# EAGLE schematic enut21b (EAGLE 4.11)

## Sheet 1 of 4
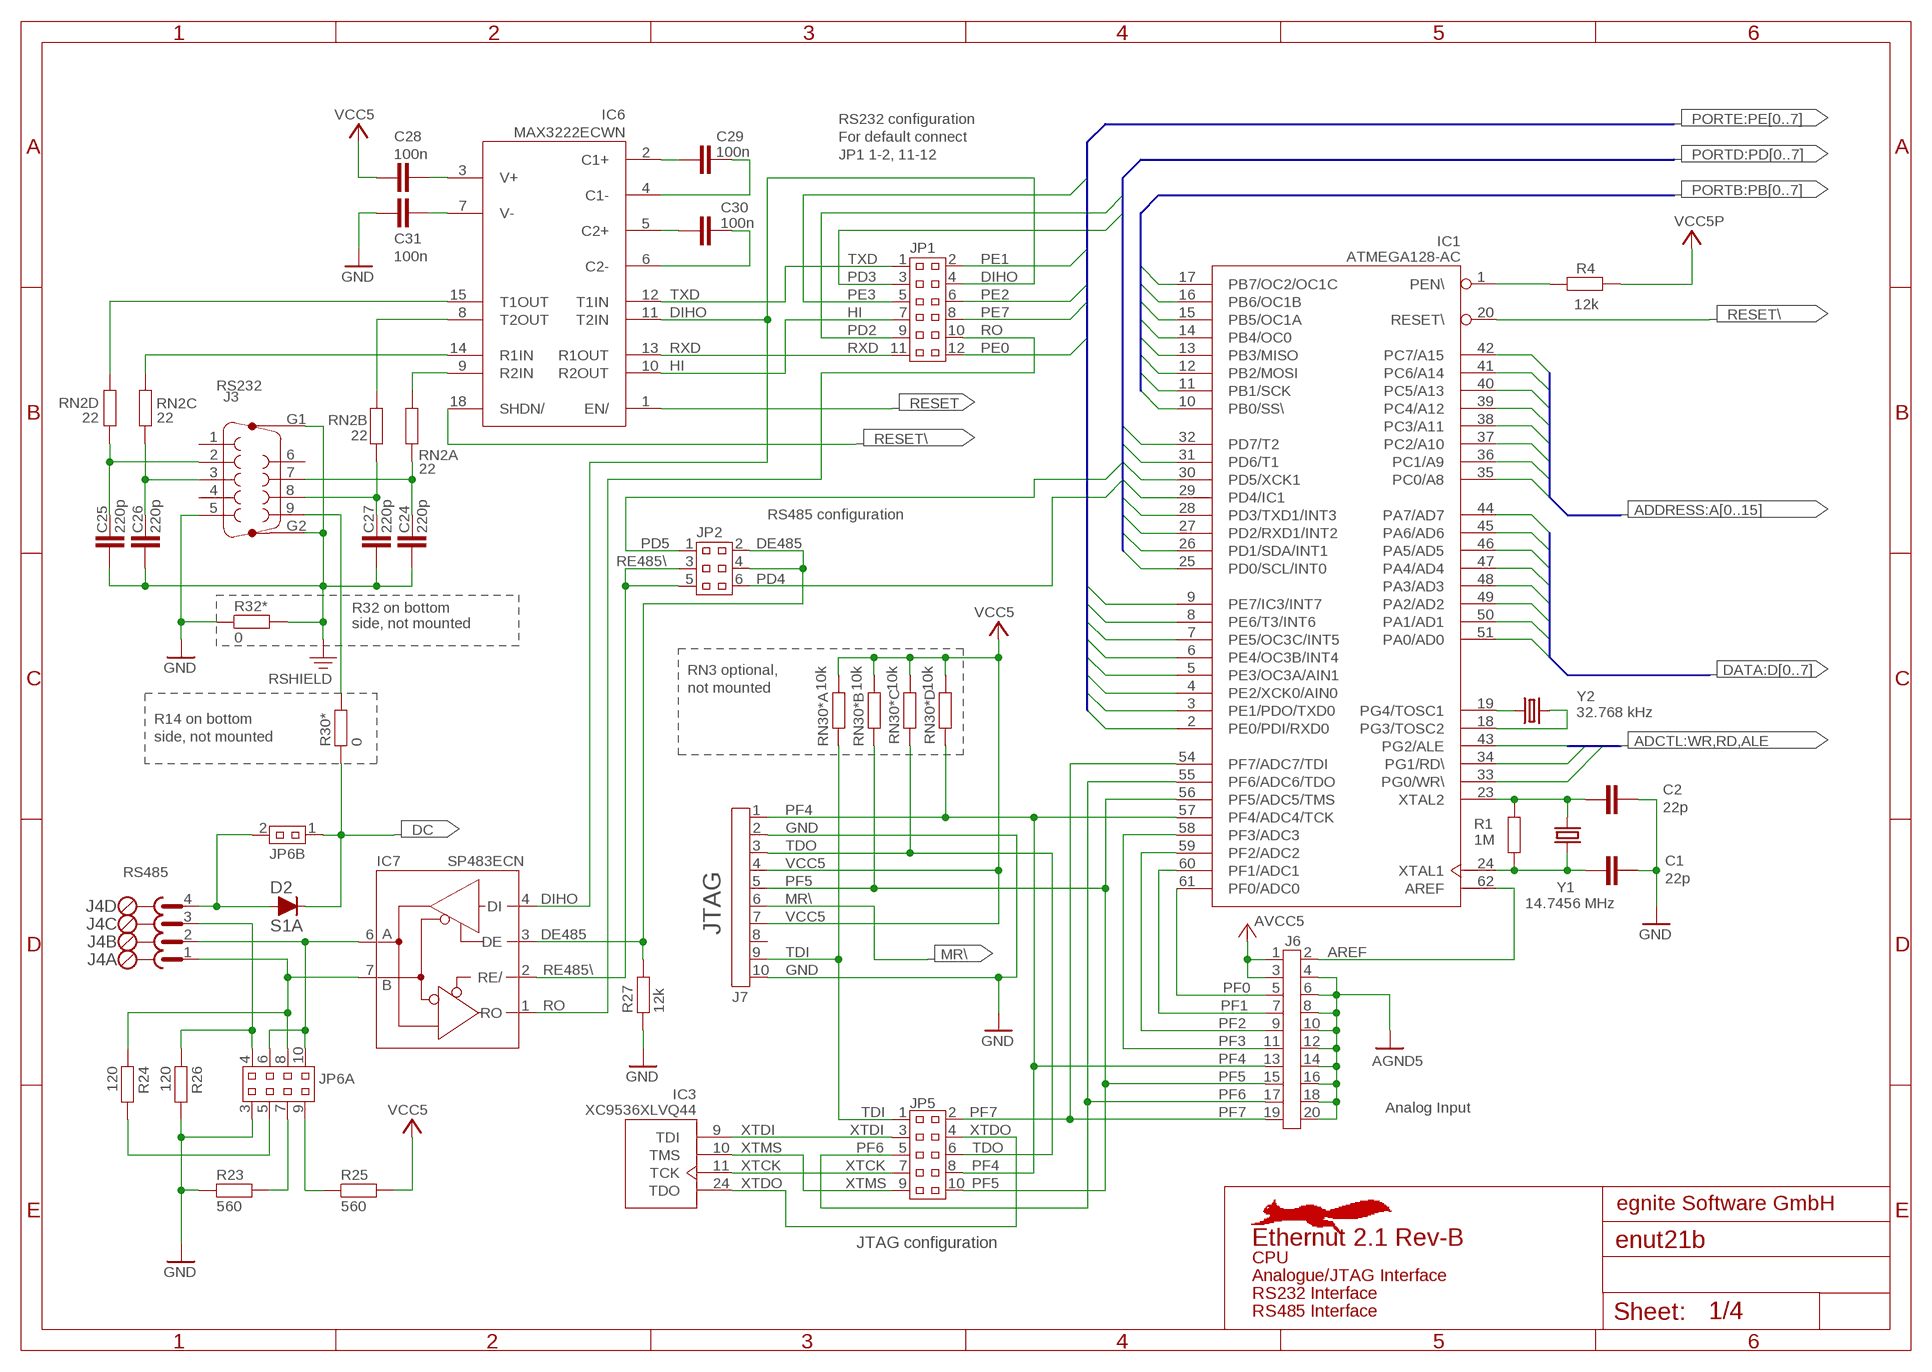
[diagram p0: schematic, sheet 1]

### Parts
C1  22p  C0603  [C0603]
C2  22p  C0603  [C0603]
C24  220p  C0603  [C0603]
C25  220p  C0603  [C0603]
C26  220p  C0603  [C0603]
C27  220p  C0603  [C0603]
C28  100n  C0603  [C0603]
C29  100n  C0603  [C0603]
C30  100n  C0603  [C0603]
C31  100n  C0603  [C0603]
D2  S1A  [SMA]
IC1  ATMEGA128-AC  [TQFP64]
IC3  XC9536XLVQ44  [VQFP44]
IC6  MAX3222ECWN  [SO18W]
IC7  SP483ECN  [SOIC8]
J3  SUBD9F  [SUBD9F]
J4  MINISK  [MINISK]
J6  PIN2X10-2.54  [SLLP2X10]
J7  ML10A  [ML10A]
JP1  JP2X6  [SLY2X6]
JP2  JP2X3  [SLY2X3]
JP5  JP2X5  [SLY2X5]
JP6  JP2X5-1E  [SLY2X5]
R1  1M  R0603  [R0603]
R4  12k  R0603  [R0603]
R23  560  R1206  [R1206]
R24  120  R1206  [R1206]
R25  560  R1206  [R1206]
R26  120  R1206  [R1206]
R27  12k  R0603  [R0603]
R30*  0  R1206  [R1206]
R32*  0  R1206  [R1206]
RN2  22  CAY16  [CAY16]
RN30*  10k  CAY16  [CAY16]
Y1  14.7456 MHz  CRYSTALHC49SM  [HC49SM]
Y2  32.768 kHz  MC-146  [MC-146]

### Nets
A8 [AddrbusH]: IC1.35(PC0/A8) ; also sheet 2
A9 [AddrbusH]: IC1.36(PC1/A9) ; also sheet 2
A10 [AddrbusH]: IC1.37(PC2/A10) ; also sheet 2
A11 [AddrbusH]: IC1.38(PC3/A11) ; also sheet 2
A12 [AddrbusH]: IC1.39(PC4/A12) ; also sheet 2
A13 [AddrbusH]: IC1.40(PC5/A13) ; also sheet 2
A14 [AddrbusH]: IC1.41(PC6/A14) ; also sheet 2
A15 [AddrbusH]: IC1.42(PC7/A15) ; also sheet 2
AGND5: J6.4 J6.6 J6.8 J6.10 J6.12 J6.14 J6.16 J6.18 J6.20 ; also sheet 4
ALE: IC1.43(PG2/ALE) ; also sheet 2
AREF: IC1.62(AREF) J6.2
AVCC5: J6.1 J6.3 ; also sheet 4
D0 [Databus]: IC1.51(PA0/AD0) ; also sheet 2,3
D1 [Databus]: IC1.50(PA1/AD1) ; also sheet 2,3
D2 [Databus]: IC1.49(PA2/AD2) ; also sheet 2,3
D3 [Databus]: IC1.48(PA3/AD3) ; also sheet 2,3
D4 [Databus]: IC1.47(PA4/AD4) ; also sheet 2,3
D5 [Databus]: IC1.46(PA5/AD5) ; also sheet 2,3
D6 [Databus]: IC1.45(PA6/AD6) ; also sheet 2,3
D7 [Databus]: IC1.44(PA7/AD7) ; also sheet 2,3
DC: D2.C JP6.1 R30*.1 ; also sheet 2,4
DCX: D2.A J4.4 JP6.2
DE485: IC7.3(DE) JP2.2 JP2.4 R27.2
DIHO: IC6.11(T2IN) IC7.4(DI) JP1.4
GND: C1.2 C2.2 C31.1 J3.5 J7.2 J7.10 JP6.3 R23.1 R26.2 R27.1 R32*.1 ; also sheet 2,3,4
HI: IC6.10(R2OUT) JP1.7
MR\: J7.6 ; also sheet 2,4
N$1: C28.2 IC6.3(V+)
N$2: J3.9 R30*.2
N$4: IC1.19(PG4/TOSC1) Y2.1
N$6: C2.1 IC1.23(XTAL2) R1.2 Y1.P$2
N$10: C1.1 IC1.24(XTAL1) R1.1 Y1.P$1
N$15: C31.2 IC6.7(V-)
N$20: JP6.9 R25.1
N$23: IC1.18(PG3/TOSC2) Y2.4
N$31: C29.1 IC6.2(C1+)
N$56: C29.2 IC6.4(C1-)
N$57: C30.2 IC6.6(C2-)
N$58: C30.1 IC6.5(C2+)
N$68: JP6.7 R23.2
N$70: JP6.5 R24.2
PB0: IC1.10(PB0/SS\) ; also sheet 2
PB1: IC1.11(PB1/SCK) ; also sheet 2
PB2: IC1.12(PB2/MOSI) ; also sheet 2
PB3: IC1.13(PB3/MISO) ; also sheet 2
PB4: IC1.14(PB4/OC0) ; also sheet 2
PB5: IC1.15(PB5/OC1A) ; also sheet 2
PB6: IC1.16(PB6/OC1B) ; also sheet 2
PB7: IC1.17(PB7/OC2/OC1C) ; also sheet 2
PD0: IC1.25(PD0/SCL/INT0) ; also sheet 2
PD1: IC1.26(PD1/SDA/INT1) ; also sheet 2
PD2: IC1.27(PD2/RXD1/INT2) JP1.9 ; also sheet 2
PD3: IC1.28(PD3/TXD1/INT3) JP1.3 ; also sheet 2
PD4: IC1.29(PD4/IC1) JP2.6 ; also sheet 2
PD5: IC1.30(PD5/XCK1) JP2.1 ; also sheet 2
PD6: IC1.31(PD6/T1) ; also sheet 2
PD7: IC1.32(PD7/T2) ; also sheet 2
PE0: IC1.2(PE0/PDI/RXD0) JP1.12 ; also sheet 2
PE1: IC1.3(PE1/PDO/TXD0) JP1.2 ; also sheet 2
PE2: IC1.4(PE2/XCK0/AIN0) JP1.6 ; also sheet 2
PE3: IC1.5(PE3/OC3A/AIN1) JP1.5 ; also sheet 2
PE4: IC1.6(PE4/OC3B/INT4) ; also sheet 2
PE5: IC1.7(PE5/OC3C/INT5) ; also sheet 2,3
PE6: IC1.8(PE6/T3/INT6) ; also sheet 2,3
PE7: IC1.9(PE7/IC3/INT7) JP1.8 ; also sheet 2
PEN\: IC1.1(PEN\) R4.1
PF0: IC1.61(PF0/ADC0) J6.5
PF1: IC1.60(PF1/ADC1) J6.7
PF2: IC1.59(PF2/ADC2) J6.9
PF3: IC1.58(PF3/ADC3) J6.11
PF4: IC1.57(PF4/ADC4/TCK) J6.13 J7.1 JP5.8 RN30*.4
PF5: IC1.56(PF5/ADC5/TMS) J6.15 J7.5 JP5.10 RN30*.2
PF6: IC1.55(PF6/ADC6/TDO) J6.17 JP5.5
PF7: IC1.54(PF7/ADC7/TDI) J6.19 JP5.2
RD\: IC1.34(PG1/RD\) ; also sheet 2,3
RE485\: IC7.2(RE/) JP2.3 JP2.5
RESET: IC6.1(EN/) ; also sheet 3,4
RESET\: IC1.20(RESET\) IC6.18(SHDN/) ; also sheet 2,4
RO: IC7.1(RO) JP1.10
RS485A: IC7.6(A) J4.2 JP6.6 JP6.10
RS485B: IC7.7(B) J4.1 JP6.8 R24.1
RSHI: IC6.9(R2IN) RN2.8
RSHIELD: C24.2 C25.2 C26.2 C27.2 J3.G1 J3.G2 R32*.2
RSHIF: C24.1 J3.7 RN2.1
RSHO: IC6.8(T2OUT) RN2.7
RSHOF: C27.1 J3.8 RN2.2
RSRXD: IC6.14(R1IN) RN2.6
RSRXDF: C26.1 J3.3 RN2.3
RSTXD: IC6.15(T1OUT) RN2.5
RSTXDF: C25.1 J3.2 RN2.4
RXD: IC6.13(R1OUT) JP1.11
SHLD485: J4.3 JP6.4 R26.1
TDI: J7.9 JP5.1 RN30*.1
TDO: J7.3 JP5.6 RN30*.3
TXD: IC6.12(T1IN) JP1.1
VCC5: C28.1 J7.4 J7.7 R25.2 RN30*.5 RN30*.6 RN30*.7 RN30*.8 ; also sheet 2,4
VCC5P: R4.2 ; also sheet 4
WR\: IC1.33(PG0/WR\) ; also sheet 2,3
XTCK: IC3.11(TCK) JP5.7
XTDI: IC3.9(TDI) JP5.3
XTDO: IC3.24(TDO) JP5.4
XTMS: IC3.10(TMS) JP5.9
Unconnected: J3.1 J3.4 J3.6 J7.8

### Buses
DATA:D[0..7]
ADDRESS:A[0..15]
ADCTL:WR\,RD\,ALE
PORTB:PB[0..7]
PORTD:PD[0..7]
PORTE:PE[0..7]

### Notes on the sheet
- RS232 configuration
- For default connect
- JP1 1-2, 11-12
- RS232
- RS485 configuration
- R32 on bottom
- side, not mounted
- RN3 optional,
- not mounted
- R14 on bottom
- side, not mounted
- RS485
- JTAG
- Analog Input
- egnite Software GmbH
- JTAG configuration | Ethernut 2.1 Rev-B
- CPU
- Analogue/JTAG Interface
- RS232 Interface
- RS485 Interface

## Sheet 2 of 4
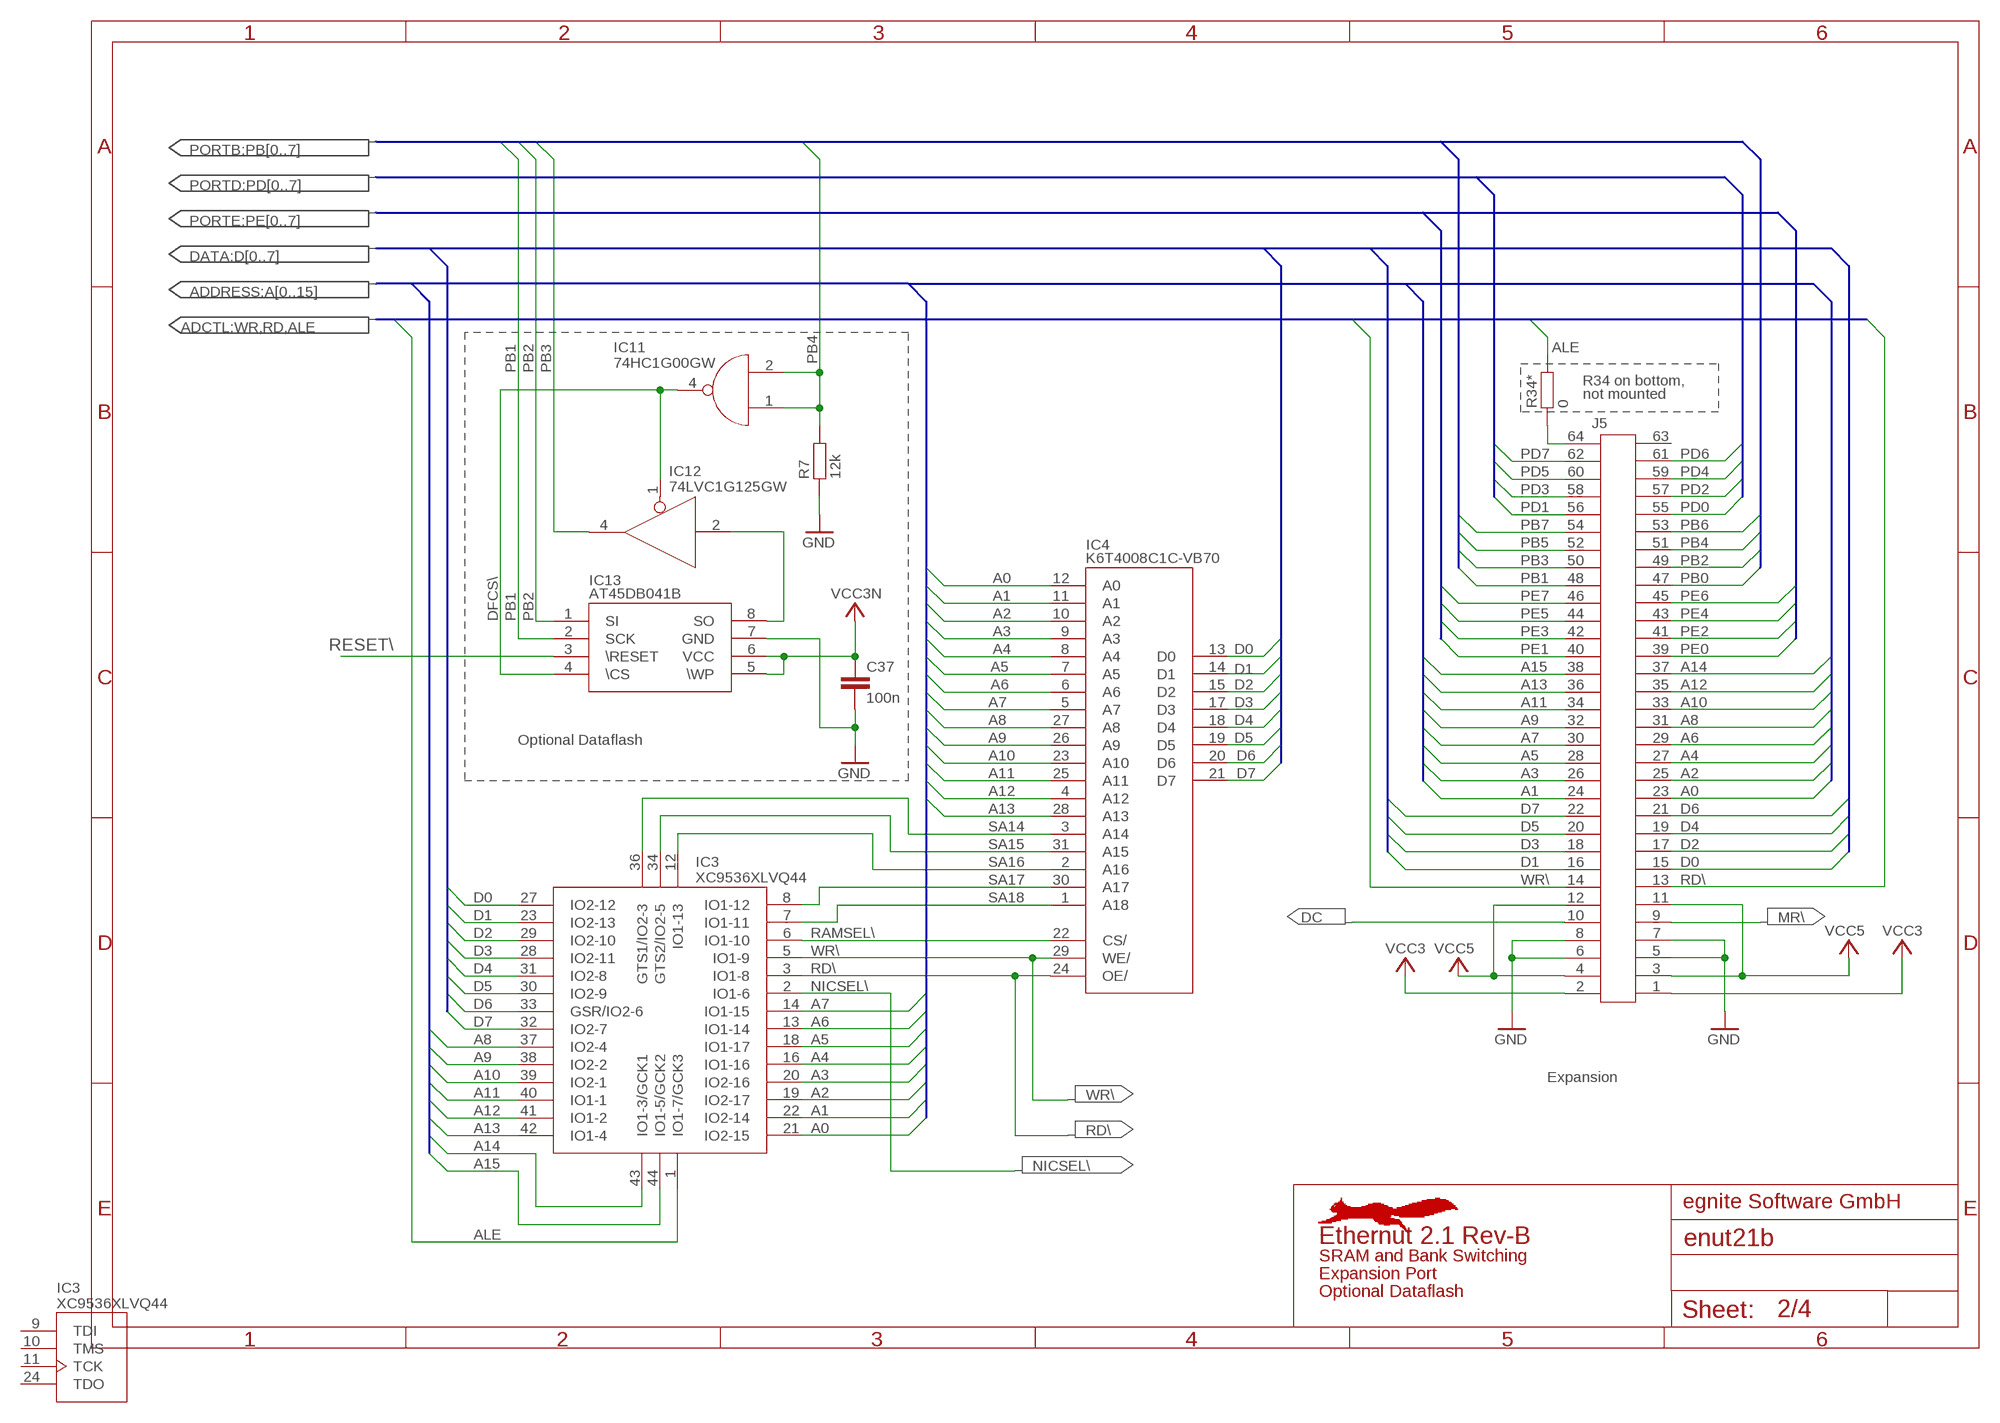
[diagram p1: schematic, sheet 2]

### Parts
C37  100n  C0603  [C0603]
IC4  K6T4008C1C-VB70  [TSOP2-32]
IC11  74HC1G00GW  [SOT353]
IC12  74LVC1G125GW  [SOT353]
IC13  AT45DB041B  [SOIC-8-209]
J5  NUTEXP  [NUTEXP]
R7  12k  R0603  [R0603]
R34*  0  R1206  [R1206]

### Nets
A0: IC3.21(IO2-15) IC4.12(A0) J5.23 ; also sheet 3
A1: IC3.22(IO2-14) IC4.11(A1) J5.24 ; also sheet 3
A2: IC3.19(IO2-17) IC4.10(A2) J5.25 ; also sheet 3
A3: IC3.20(IO2-16) IC4.9(A3) J5.26 ; also sheet 3
A4: IC3.16(IO1-16) IC4.8(A4) J5.27 ; also sheet 3
A5: IC3.18(IO1-17) IC4.7(A5) J5.28
A6: IC3.13(IO1-14) IC4.6(A6) J5.29
A7: IC3.14(IO1-15) IC4.5(A7) J5.30
A8 [AddrbusH]: IC3.37(IO2-4) IC4.27(A8) J5.31 ; also sheet 1
A9 [AddrbusH]: IC3.38(IO2-2) IC4.26(A9) J5.32 ; also sheet 1
A10 [AddrbusH]: IC3.39(IO2-1) IC4.23(A10) J5.33 ; also sheet 1
A11 [AddrbusH]: IC3.40(IO1-1) IC4.25(A11) J5.34 ; also sheet 1
A12 [AddrbusH]: IC3.41(IO1-2) IC4.4(A12) J5.35 ; also sheet 1
A13 [AddrbusH]: IC3.42(IO1-4) IC4.28(A13) J5.36 ; also sheet 1
A14 [AddrbusH]: IC3.43(IO1-3/GCK1) J5.37 ; also sheet 1
A15 [AddrbusH]: IC3.44(IO1-5/GCK2) J5.38 ; also sheet 1
ALE: IC3.1(IO1-7/GCK3) R34*.2 ; also sheet 1
D0 [Databus]: IC3.27(IO2-12) IC4.13(D0) J5.15 ; also sheet 1,3
D1 [Databus]: IC3.23(IO2-13) IC4.14(D1) J5.16 ; also sheet 1,3
D2 [Databus]: IC3.29(IO2-10) IC4.15(D2) J5.17 ; also sheet 1,3
D3 [Databus]: IC3.28(IO2-11) IC4.17(D3) J5.18 ; also sheet 1,3
D4 [Databus]: IC3.31(IO2-8) IC4.18(D4) J5.19 ; also sheet 1,3
D5 [Databus]: IC3.30(IO2-9) IC4.19(D5) J5.20 ; also sheet 1,3
D6 [Databus]: IC3.33(GSR/IO2-6) IC4.20(D6) J5.21 ; also sheet 1,3
D7 [Databus]: IC3.32(IO2-7) IC4.21(D7) J5.22 ; also sheet 1,3
DC: J5.10 ; also sheet 1,4
DFCS\: IC11.4(O) IC12.1(OE) IC13.4(\CS)
DFSO: IC12.2(I) IC13.8(SO)
EXPALE: J5.64 R34*.1
GND: C37.2 IC13.7(GND) J5.5 J5.6 J5.7 J5.8 R7.1 ; also sheet 1,3,4
MR\: J5.9 ; also sheet 1,4
NICSEL\: IC3.2(IO1-6) ; also sheet 3
PB0: J5.47 ; also sheet 1
PB1: IC13.2(SCK) J5.48 ; also sheet 1
PB2: IC13.1(SI) J5.49 ; also sheet 1
PB3: IC12.4(O) J5.50 ; also sheet 1
PB4: IC11.1(I0) IC11.2(I1) J5.51 R7.2 ; also sheet 1
PB5: J5.52 ; also sheet 1
PB6: J5.53 ; also sheet 1
PB7: J5.54 ; also sheet 1
PD0: J5.55 ; also sheet 1
PD1: J5.56 ; also sheet 1
PD2: J5.57 ; also sheet 1
PD3: J5.58 ; also sheet 1
PD4: J5.59 ; also sheet 1
PD5: J5.60 ; also sheet 1
PD6: J5.61 ; also sheet 1
PD7: J5.62 ; also sheet 1
PE0: J5.39 ; also sheet 1
PE1: J5.40 ; also sheet 1
PE2: J5.41 ; also sheet 1
PE3: J5.42 ; also sheet 1
PE4: J5.43 ; also sheet 1
PE5: J5.44 ; also sheet 1,3
PE6: J5.45 ; also sheet 1,3
PE7: J5.46 ; also sheet 1
RAMSEL\: IC3.6(IO1-10) IC4.22(CS/)
RD\: IC3.3(IO1-8) IC4.24(OE/) J5.13 ; also sheet 1,3
RESET\: IC13.3(\RESET) ; also sheet 1,4
SA14: IC3.36(GTS1/IO2-3) IC4.3(A14)
SA15: IC3.34(GTS2/IO2-5) IC4.31(A15)
SA16: IC3.12(IO1-13) IC4.2(A16)
SA17: IC3.8(IO1-12) IC4.30(A17)
SA18: IC3.7(IO1-11) IC4.1(A18)
VCC3: J5.1 J5.2 ; also sheet 4
VCC3N: C37.1 IC13.5(\WP) IC13.6(VCC) ; also sheet 3,4
VCC5: J5.3 J5.4 J5.11 J5.12 ; also sheet 1,4
WR\: IC3.5(IO1-9) IC4.29(WE/) J5.14 ; also sheet 1,3
Unconnected: J5.63

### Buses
ADDRESS:A[0..15]
DATA:D[0..7]
ADCTL:WR\,RD\,ALE
PORTE:PE[0..7]
PORTD:PD[0..7]
PORTB:PB[0..7]

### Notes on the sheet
- R34 on bottom,
- not mounted
- Optional Dataflash
- Expansion
- egnite Software GmbH
- Ethernut 2.1 Rev-B
- SRAM and Bank Switching
- Expansion Port
- Optional Dataflash

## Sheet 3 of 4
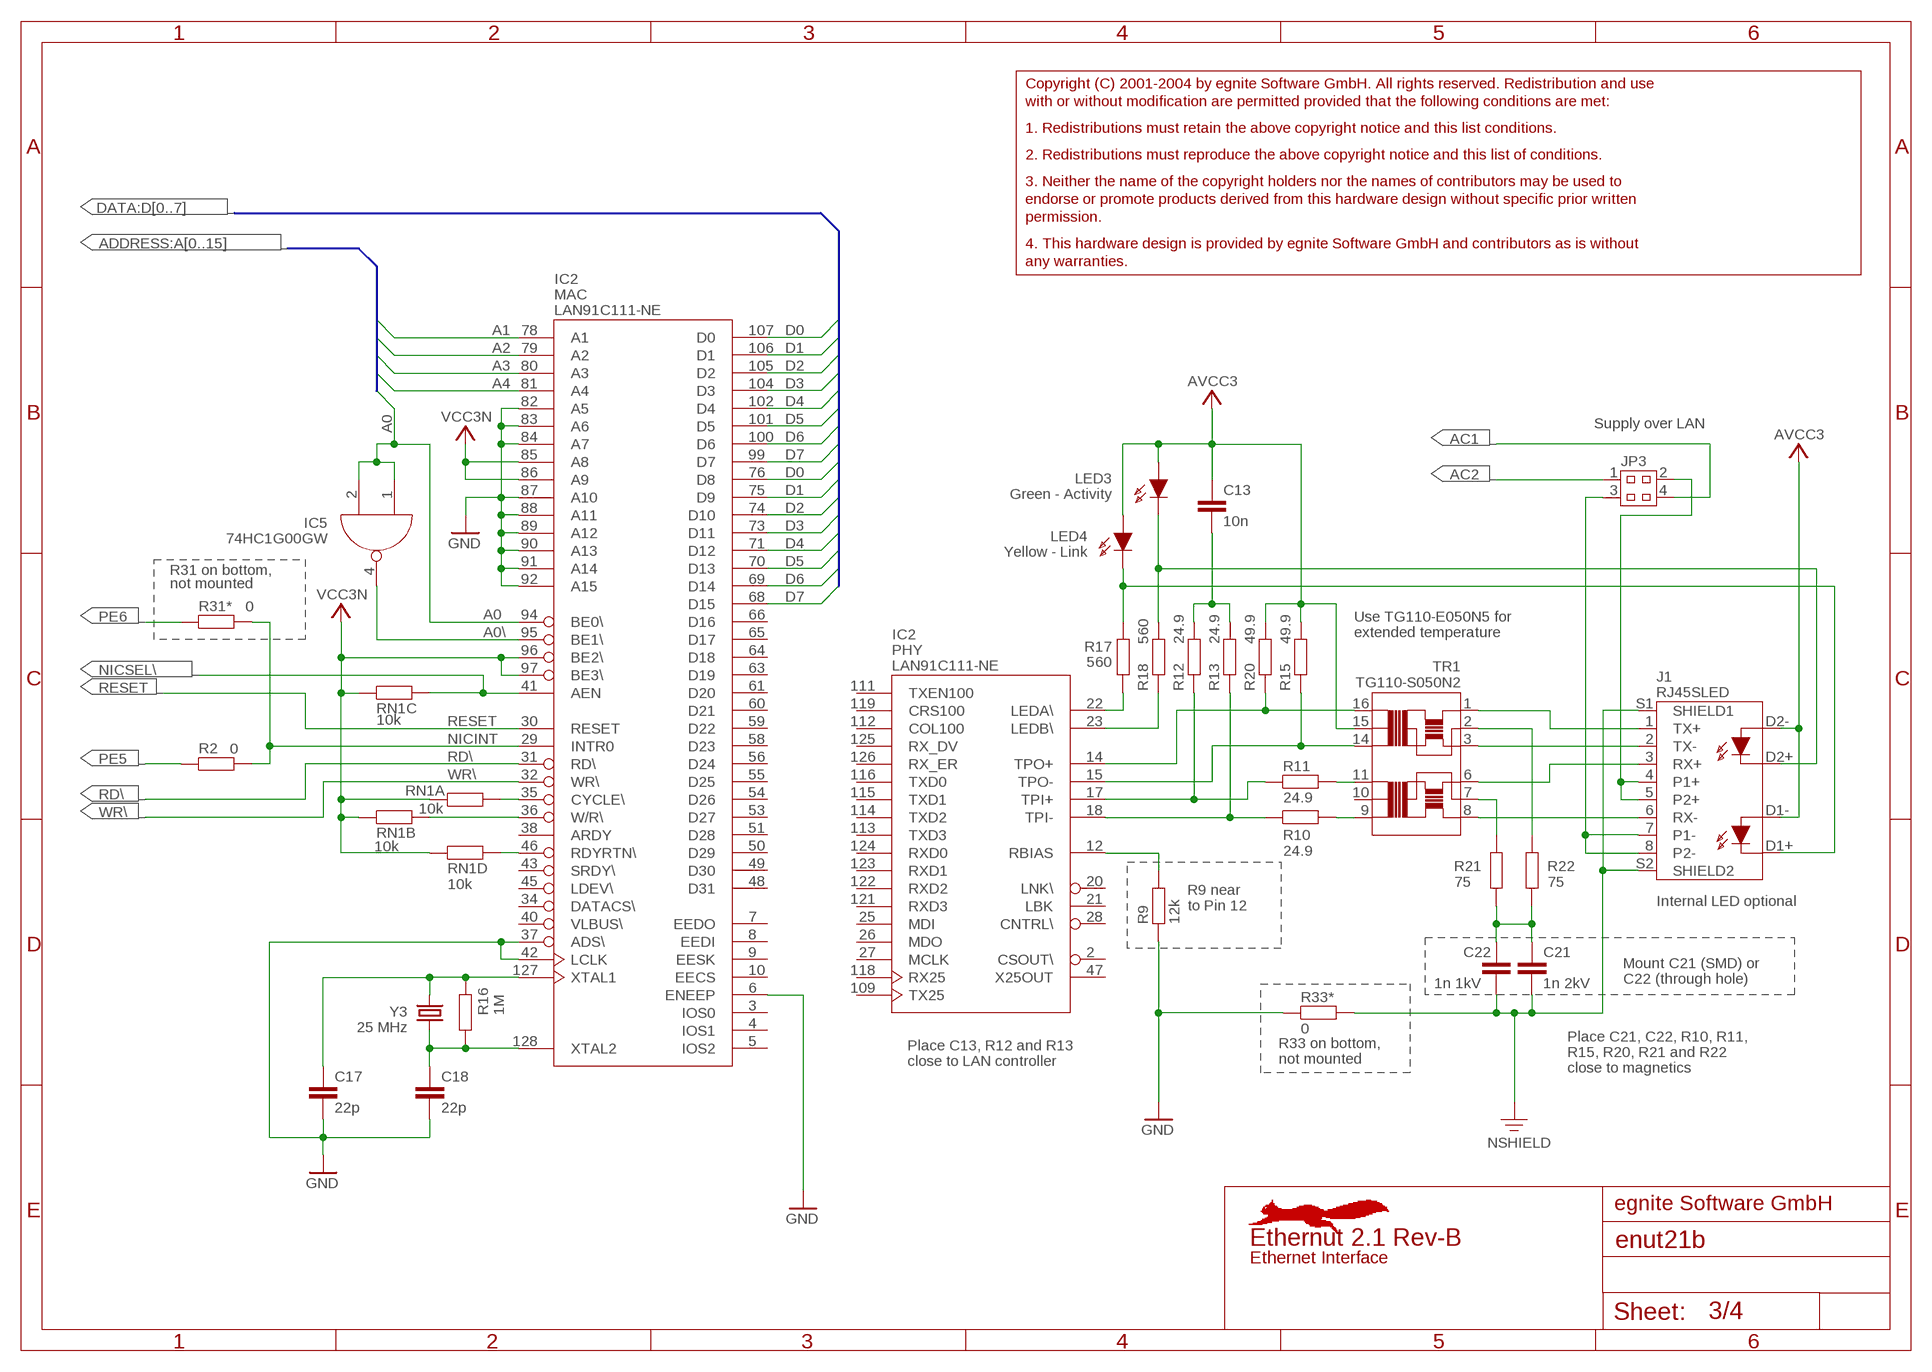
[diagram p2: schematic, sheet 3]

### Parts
C13  10n  C0603  [C0603]
C17  22p  C0603  [C0603]
C18  22p  C0603  [C0603]
C21  1n 2kV  C5.0  [C5.0]
C22  1n 1kV  RCL_C-EUC1812  [RCL_C1812]
IC2  LAN91C111-NE  [TQFP128]
IC5  74HC1G00GW  [SOT353]
J1  RJ45SLED  [RJ45S]
JP3  JP2X2  [SLY2X2]
LED3  LTST-T670KGKT  [P-LCC-2]
LED4  LTST-T670KSKT  [P-LCC-2]
R2  0  R1206  [R1206]
R9  12k  R0603  [R0603]
R10  24.9  R0603  [R0603]
R11  24.9  R0603  [R0603]
R12  24.9  R0603  [R0603]
R13  24.9  R0603  [R0603]
R15  49.9  R0603  [R0603]
R16  1M  R0603  [R0603]
R17  560  R1206  [R1206]
R18  560  R1206  [R1206]
R20  49.9  R0603  [R0603]
R21  75  R1206  [R1206]
R22  75  R1206  [R1206]
R31*  0  R1206  [R1206]
R33*  0  R1206  [R1206]
RN1  10k  CAY16  [CAY16]
TR1  TG110-S050N2  [SOIC16-12TR]
Y3  25 MHz  CRYSTALHC49SM  [HC49SM]

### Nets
A0: IC2.94(MAC:BE0\) IC5.1(I0) IC5.2(I1) ; also sheet 2
A0\: IC2.95(MAC:BE1\) IC5.4(O)
A1: IC2.78(MAC:A1) ; also sheet 2
A2: IC2.79(MAC:A2) ; also sheet 2
A3: IC2.80(MAC:A3) ; also sheet 2
A4: IC2.81(MAC:A4) ; also sheet 2
AC1 [Supply1A]: JP3.4 ; also sheet 4
AC2 [Supply1A]: JP3.1 ; also sheet 4
AVCC3: C13.1 J1.D1-(A1) J1.D2-(A2) LED3.A LED4.A R15.2 R20.2 TR1.15 ; also sheet 4
CYCLE\: IC2.35(MAC:CYCLE\) RN1.8
D0 [Databus]: IC2.76(MAC:D8) IC2.107(MAC:D0) ; also sheet 1,2
D1 [Databus]: IC2.75(MAC:D9) IC2.106(MAC:D1) ; also sheet 1,2
D2 [Databus]: IC2.74(MAC:D10) IC2.105(MAC:D2) ; also sheet 1,2
D3 [Databus]: IC2.73(MAC:D11) IC2.104(MAC:D3) ; also sheet 1,2
D4 [Databus]: IC2.71(MAC:D12) IC2.102(MAC:D4) ; also sheet 1,2
D5 [Databus]: IC2.70(MAC:D13) IC2.101(MAC:D5) ; also sheet 1,2
D6 [Databus]: IC2.69(MAC:D14) IC2.100(MAC:D6) ; also sheet 1,2
D7 [Databus]: IC2.68(MAC:D15) IC2.99(MAC:D7) ; also sheet 1,2
GND: C17.2 C18.2 IC2.6(MAC:ENEEP) IC2.37(MAC:ADS\) IC2.42(MAC:LCLK) IC2.82(MAC:A5) IC2.83(MAC:A6) IC2.84(MAC:A7) IC2.87(MAC:A10) IC2.88(MAC:A11) IC2.89(MAC:A12) IC2.90(MAC:A13) IC2.91(MAC:A14) IC2.92(MAC:A15) R9.1 R33*.1 ; also sheet 1,2,4
LEDA\: J1.D1+(C1) LED4.C R17.2
LEDB\: J1.D2+(C2) LED3.C R18.2
N$5: J1.1(TX+) TR1.1
N$12: J1.2(TX-) TR1.3
N$22: J1.3(RX+) TR1.6
N$24: J1.6(RX-) TR1.8
N$25: IC2.12(PHY:RBIAS) R9.2
N$26: R21.2 TR1.7
N$27: R10.2 TR1.9
N$32: R22.2 TR1.2
N$33: R11.2 TR1.11
N$44: C21.1 C22.1 R21.1 R22.1
NICINT: IC2.29(MAC:INTR0) R2.2 R31*.2
NICSEL\: IC2.41(MAC:AEN) RN1.6 ; also sheet 2
NICWR\: IC2.36(MAC:W/R\) RN1.7
NLEDA\: IC2.22(PHY:LEDA\) R17.1
NLEDB\: IC2.23(PHY:LEDB\) R18.1
NSHIELD: C21.2 C22.2 J1.S1(SHIELD1) J1.S2(SHIELD2) R33*.2
NXTAL1: C17.1 IC2.127(MAC:XTAL1) R16.2 Y3.P$2
NXTAL2: C18.1 IC2.128(MAC:XTAL2) R16.1 Y3.P$1
PE5: R2.1 ; also sheet 1,2
PE6: R31*.1 ; also sheet 1,2
POE+ [Supply1A]: J1.7(P1-) J1.8(P2-) JP3.3
POE- [Supply1A]: J1.4(P1+) J1.5(P2+) JP3.2
RD\: IC2.31(MAC:RD\) ; also sheet 1,2
RDYRTN\: IC2.46(MAC:RDYRTN\) RN1.5
RESET: IC2.30(MAC:RESET) ; also sheet 1,4
RRCUP: C13.2 R12.2 R13.2
TPI+: IC2.17(PHY:TPI+) R11.1 R12.1
TPI-: IC2.18(PHY:TPI-) R10.1 R13.1
TPO+: IC2.14(PHY:TPO+) R20.1 TR1.16
TPO-: IC2.15(PHY:TPO-) R15.1 TR1.14
VCC3N: IC2.85(MAC:A8) IC2.86(MAC:A9) IC2.96(MAC:BE2\) IC2.97(MAC:BE3\) RN1.1 RN1.2 RN1.3 RN1.4 ; also sheet 2,4
WR\: IC2.32(MAC:WR\) ; also sheet 1,2
Unconnected: TR1.10

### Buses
DATA:D[0..7]
ADDRESS:A[0..15]

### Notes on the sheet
- Copyright (C) 2001-2004 by egnite Software GmbH. All rights reserved. Redistribution and use
- with or without modification are permitted provided that the following conditions are met:
- 1. Redistributions must retain the above copyright notice and this list conditions.
- 2. Redistributions must reproduce the above copyright notice and this list of conditions.
- 3. Neither the name of the copyright holders nor the names of contributors may be used to
- endorse or promote products derived from this hardware design without specific prior written
- permission.
- 4. This hardware design is provided by egnite Software GmbH and contributors as is without
- any warranties.
- Supply over LAN
- Green - Activity
- Yellow - Link
- R31 on bottom,
- not mounted
- Use TG110-E050N5 for
- extended temperature
- R9 near
- Internal LED optional
- to Pin 12
- Mount C21 (SMD) or
- C22 (through hole)
- Place C21, C22, R10, R11,
- Place C13, R12 and R13 | R33 on bottom,
- R15, R20, R21 and R22
- close to LAN controller | not mounted
- close to magnetics
- egnite Software GmbH
- Ethernut 2.1 Rev-B
- Ethernet Interface

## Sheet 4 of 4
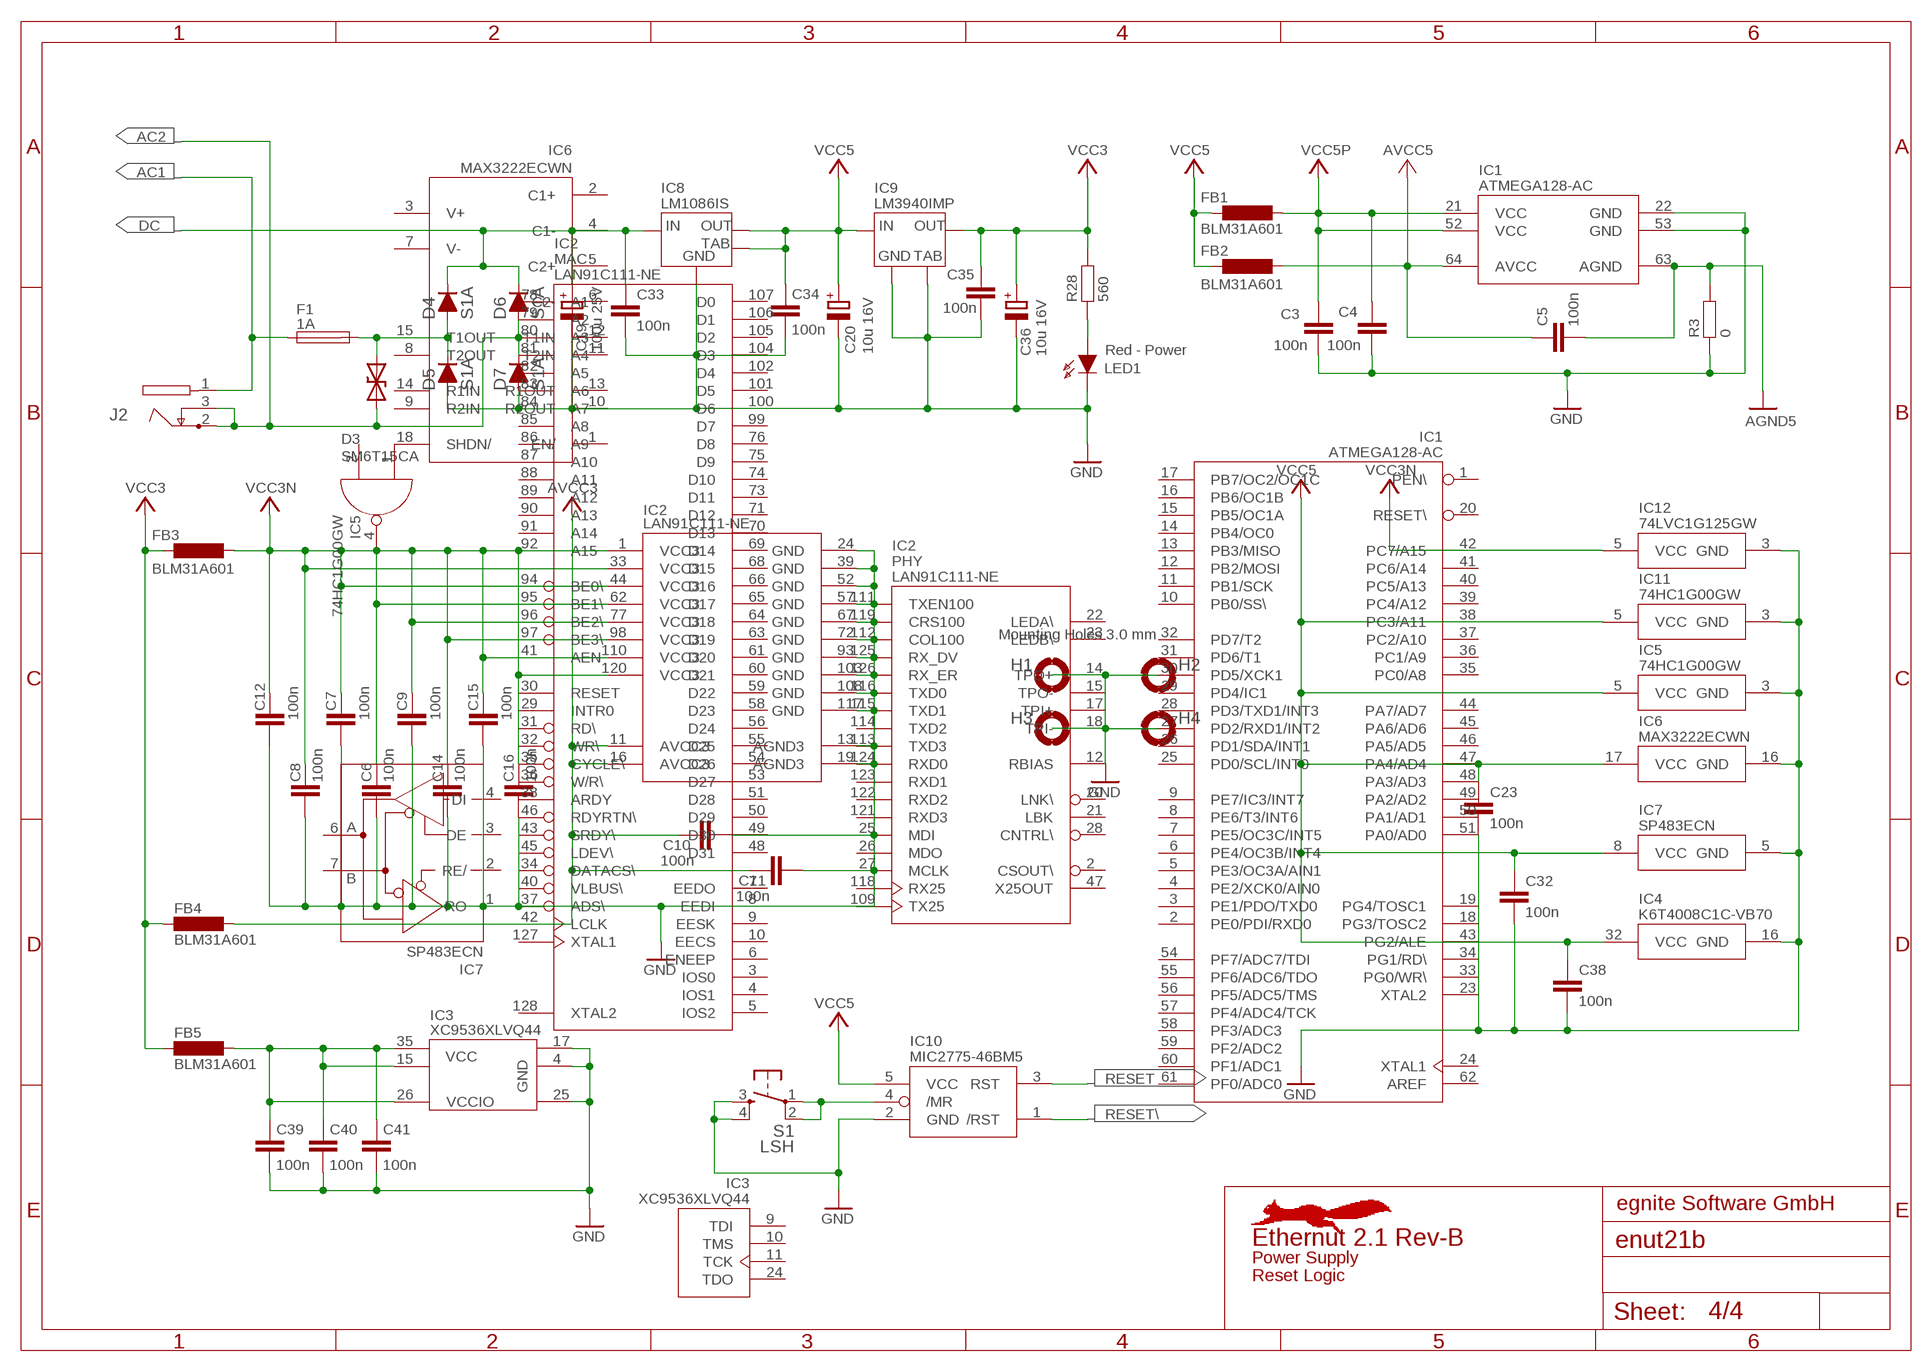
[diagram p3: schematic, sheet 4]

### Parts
C3  100n  C0603  [C0603]
C4  100n  C0603  [C0603]
C5  100n  C0603  [C0603]
C6  100n  C0603  [C0603]
C7  100n  C0603  [C0603]
C8  100n  C0603  [C0603]
C9  100n  C0603  [C0603]
C10  100n  C0603  [C0603]
C11  100n  C0603  [C0603]
C12  100n  C0603  [C0603]
C14  100n  C0603  [C0603]
C15  100n  C0603  [C0603]
C16  100n  C0603  [C0603]
C19  100u 25V  ALUCAP6.3  [ALUC6.3]
C20  10u 16V  ALUCAP4.0  [ALUC4.0]
C23  100n  C0603  [C0603]
C32  100n  C0603  [C0603]
C33  100n  C0603  [C0603]
C34  100n  C0603  [C0603]
C35  100n  C0603  [C0603]
C36  10u 16V  ALUCAP4.0  [ALUC4.0]
C38  100n  C0603  [C0603]
C39  100n  C0603  [C0603]
C40  100n  C0603  [C0603]
C41  100n  C0603  [C0603]
D3  SM6T15CA  SM6T  [SMB]
D4  S1A  [SMA]
D5  S1A  [SMA]
D6  S1A  [SMA]
D7  S1A  [SMA]
F1  1A  OMNI-BLOK  [OMNI-BLOK]
FB1  BLM31A601  BLM31A  [BLM31]
FB2  BLM31A601  BLM31A  [BLM31]
FB3  BLM31A601  BLM31A  [BLM31]
FB4  BLM31A601  BLM31A  [BLM31]
FB5  BLM31A601  BLM31A  [BLM31]
H1  MOUNT3  [MOUNT3]
H2  MOUNT3  [MOUNT3]
H3  MOUNT3  [MOUNT3]
H4  MOUNT3  [MOUNT3]
IC8  LM1086IS  [DDPAK-ST]
IC9  LM3940IMP  [SOT-223]
IC10  MIC2775-46BM5  [SOT23-5L]
J2  DC2.1  [DC2.1]
LED1  LTST-T670KRKT  [P-LCC-2]
R3  0  R1206  [R1206]
R28  560  R1206  [R1206]
S1  LSH  [LSH]

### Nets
AC1 [Supply1A]: F1.1 J2.1 ; also sheet 3
AC2 [Supply1A]: D3.A D6.A D7.C J2.2 J2.3 ; also sheet 3
ACF: D3.C D4.A D5.C F1.2
AGND5: C5.2 IC1.63(AGND) R3.2 ; also sheet 1
AVCC3: C10.1 C11.1 FB4.1 IC2.11(PWR:AVCC3) IC2.16(PWR:AVCC3) ; also sheet 3
AVCC5: C5.1 FB2.2 IC1.64(AVCC) ; also sheet 1
DC: C19.+ C33.1 D4.C D6.C IC8.3(IN) ; also sheet 1,2
GND: C3.2 C4.2 C6.2 C7.2 C8.2 C9.2 C10.2 C11.2 C12.2 C14.2 C15.2 C16.2 C19.- C20.- C23.2 C32.2 C33.2 C34.2 C35.2 C36.- C38.2 C39.2 C40.2 C41.2 D5.A D7.A H1.B3,0(MOUNT) H2.B3,0(MOUNT) H3.B3,0(MOUNT) H4.B3,0(MOUNT) IC1.22(GND) IC1.53(GND) IC2.13(PWR:AGND3) IC2.19(PWR:AGND3) IC2.24(PWR:GND) IC2.39(PWR:GND) IC2.52(PWR:GND) IC2.57(PWR:GND) IC2.67(PWR:GND) IC2.72(PWR:GND) IC2.93(PWR:GND) IC2.103(PWR:GND) IC2.108(PWR:GND) IC2.117(PWR:GND) IC3.4(GND) IC3.17(GND) IC3.25(GND) IC4.16(GND) IC5.3(GND) IC6.16(GND) IC7.5(GND) IC8.1(GND) IC9.2(GND) IC9.4(TAB) IC10.2(GND) IC11.3(GND) IC12.3(GND) LED1.C R3.1 S1.3(S) S1.4(S1) ; also sheet 1,2,3
MR\: IC10.4(/MR) S1.1(P) S1.2(P1) ; also sheet 1,2
N$43: LED1.A R28.1
RESET: IC10.3(RST) ; also sheet 1,3
RESET\: IC10.1(/RST) ; also sheet 1,2
VCC3: C35.1 C36.+ FB3.1 FB4.2 FB5.2 IC9.3(OUT) R28.2 ; also sheet 2
VCC3N: C6.1 C7.1 C8.1 C9.1 C12.1 C14.1 C15.1 C16.1 FB3.2 IC2.1(PWR:VCC3) IC2.33(PWR:VCC3) IC2.44(PWR:VCC3) IC2.62(PWR:VCC3) IC2.77(PWR:VCC3) IC2.98(PWR:VCC3) IC2.110(PWR:VCC3) IC2.120(PWR:VCC3) IC12.5(VCC) ; also sheet 2,3
VCC3X: C39.1 C40.1 C41.1 FB5.1 IC3.15(VCCINT) IC3.26(VCCIO) IC3.35(VCCINT)
VCC5: C20.+ C23.1 C32.1 C34.1 C38.1 FB1.1 FB2.1 IC4.32(VCC) IC5.5(VCC) IC6.17(VCC) IC7.8(VCC) IC8.2(OUT) IC8.4(TAB) IC9.1(IN) IC10.5(VCC) IC11.5(VCC) ; also sheet 1,2
VCC5P: C3.1 C4.1 FB1.2 IC1.21(VCC) IC1.52(VCC) ; also sheet 1
Unconnected: IC2.2(PHY:CSOUT\) IC2.3(MAC:IOS0) IC2.4(MAC:IOS1) IC2.5(MAC:IOS2) IC2.7(MAC:EEDO) IC2.8(MAC:EEDI) IC2.9(MAC:EESK) IC2.10(MAC:EECS) IC2.20(PHY:LNK\) IC2.21(PHY:LBK) IC2.25(PHY:MDI) IC2.26(PHY:MDO) IC2.27(PHY:MCLK) IC2.28(PHY:CNTRL\) IC2.34(MAC:DATACS\) IC2.38(MAC:ARDY) IC2.40(MAC:VLBUS\) IC2.43(MAC:SRDY\) IC2.45(MAC:LDEV\) IC2.47(PHY:X25OUT) IC2.48(MAC:D31) IC2.49(MAC:D30) IC2.50(MAC:D29) IC2.51(MAC:D28) IC2.53(MAC:D27) IC2.54(MAC:D26) IC2.55(MAC:D25) IC2.56(MAC:D24) IC2.58(MAC:D23) IC2.59(MAC:D22) IC2.60(MAC:D21) IC2.61(MAC:D20) IC2.63(MAC:D19) IC2.64(MAC:D18) IC2.65(MAC:D17) IC2.66(MAC:D16) IC2.109(PHY:TX25) IC2.111(PHY:TXEN100) IC2.112(PHY:COL100) IC2.113(PHY:TXD3) IC2.114(PHY:TXD2) IC2.115(PHY:TXD1) IC2.116(PHY:TXD0) IC2.118(PHY:RX25) IC2.119(PHY:CRS100) IC2.121(PHY:RXD3) IC2.122(PHY:RXD2) IC2.123(PHY:RXD1) IC2.124(PHY:RXD0) IC2.125(PHY:RX_DV) IC2.126(PHY:RX_ER)

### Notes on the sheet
- Red - Power
- Mounting Holes 3.0 mm
- egnite Software GmbH
- Ethernut 2.1 Rev-B
- Power Supply
- Reset Logic

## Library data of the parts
C1-C18 C21 C23-C35 C37-C41 = enut202:C: Capacitor
C19 C20 C36 = enut202:ALUCAP: Capacitor Electrolyt
C22 = enut202:RCL_C-EU: CAPACITOR, European symbol
D2 D4-D7 = enut202:S1A: Diode Rectifier
D3 = enut202:SM6T: Bidirectional Transient Voltage Suppressor
F1 = enut202:OMNI-BLOK: Littlefuse OMNI-BLOK Fuseholder with Fuse
FB1-FB5 = enut202:BLM31A: Inductivity Murata
H1-H4 = enut202:MOUNT3: No part, mounting hole
IC1 = enut202:ATMEGA128: IC - Atmel AVR Microcontroller
IC2 = enut202:LAN91C111: SMSC 10/100 Non-PCI Ethernet MAC + PHY
IC3 = enut202:XC9536XL: IC - CPLD, Xlinx 36 macrocells 34 user I/O pins
IC4 = enut202:K6T4008C1C: Samsung SRAM 512k x 8
IC5 IC11 = enut202:74*1G00: IC - Picogate, Philips (Fairchild)
IC6 = enut202:MAX3222E: Maxim RS232 Driver
IC7 = enut202:SP483E: Sipex RS485 Driver
IC8 = enut202:LM1086: National Voltage Regulator
IC9 = enut202:LM3940: National Voltage Regulator
IC10 = enut202:MIC2775-*: Micrel Voltage Supervisor
IC12 = enut202:74*1G125: IC - Picogate, Philips (Fairchild) Bus buffer/line drivers; 3-state
IC13 = enut202:AT45DB041B: IC - Atmel Dataflash
J1 = enut202:RJ45SLED: Connector - RJ45 (NO LED)
J2 = enut202:DC: Connector - DC 2.1 mm
J3 = enut202:SUBD9F: Connector DB-9
J4 = enut202:MINISK: Connector - Phoenix Micro Screw Terminal
J5 = enut202:NUTEXP: Connector - Pin Header
J6 = enut202:PIN2X10: Connector - Pinhead
J7 = enut202:ML10: Connector 10-pin
JP1 = enut202:JP2X6: Jumper 2mm
JP2 = enut202:JP2X3: Jumper 2mm
JP3 = enut202:JP2X2: Jumper 2mm
JP5 = enut202:JP2X5: Jumper 2mm
JP6 = enut202:JP2X5-1E: Jumper 2mm
LED1 LED3 LED4 = enut202:LTST-T670: SMD LED
R1-R4 R7 R9-R13 R15-R18 R20-R28 R30* R31* R32* R33* R34* = enut202:R: Resistor
RN1 RN2 RN30* = enut202:CAY16: Resistor Array
S1 = enut202:LSH: Switch - Schurter
TR1 = enut202:TG110-S050: Ethernet Transformer, Halo
Y1 Y3 = enut202:CRYSTAL: Crystal
Y2 = enut202:MC-146: Clock Crystal SMD

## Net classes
1 Supply1A: width 0.61 mm
4 Ground: width 0.406 mm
